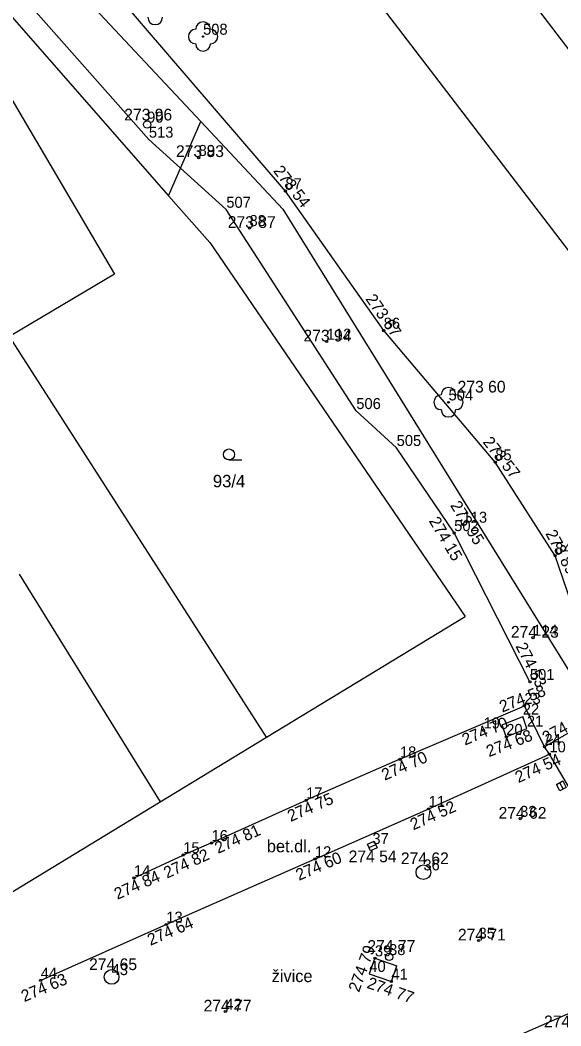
# Model space of a CAD drawing. Extents: x -492379 to -491966, y -1126153 to -1125860.
# Drawn here: x -492207.01 to -492184.88, y -1126038.78 to -1125997.58 of the extents above; entities that cross this region are included whole.
import ezdxf

# ---------------------------------------------------------------- set-up
doc = ezdxf.new("R2010")
doc.units = 0
for name, color, linetype in [('body', 7, 'Continuous'), ('hrana svahu', 7, 'Continuous'), ('kanalizace', 7, 'Continuous'), ('katastrální mapa', 7, 'Continuous'), ('ostatní objekty', 7, 'Continuous'), ('plot', 7, 'Continuous'), ('plyn', 7, 'Continuous'), ('podrobný výškový bod', 7, 'Continuous'), ('popis ploch', 7, 'Continuous'), ('rozhraní ploch', 7, 'Continuous'), ('silové vedení', 7, 'Continuous'), ('vodovod', 7, 'Continuous'), ('vstup na pozemek', 7, 'Continuous'), ('výšky', 7, 'Continuous'), ('čísla bodů', 7, 'Continuous')]:
    doc.layers.add(name, color=color, linetype=linetype)

msp = doc.modelspace()

# ---------------------------------------------------------------- linework, layer by layer
at = {"layer": 'body'}
for p, q in [((-492199.521, -1125998.258), (-492199.521, -1125998.258)), ((-492201.81, -1126001.858), (-492201.81, -1126001.858)), ((-492201.739, -1126002.474), (-492201.739, -1126002.474)), ((-492199.703, -1126003.222), (-492199.703, -1126003.222)), ((-492196.15, -1126004.585), (-492196.15, -1126004.585)), ((-492198.57, -1126005.345), (-492198.57, -1126005.345)), ((-492197.621, -1126006.096), (-492197.621, -1126006.096)), ((-492192.127, -1126010.3), (-492192.127, -1126010.3)), ((-492194.458, -1126010.749), (-492194.458, -1126010.749)), ((-492189.476, -1126013.237), (-492189.476, -1126013.237)), ((-492193.25, -1126013.59), (-492193.25, -1126013.59)), ((-492191.598, -1126015.101), (-492191.598, -1126015.101)), ((-492187.562, -1126015.688), (-492187.562, -1126015.688)), ((-492188.9, -1126018.244), (-492188.9, -1126018.244)), ((-492189.244, -1126018.589), (-492189.244, -1126018.589)), ((-492185.109, -1126019.52), (-492185.109, -1126019.52)), ((-492186.014, -1126022.877), (-492186.014, -1126022.877)), ((-492186.144, -1126024.687), (-492186.144, -1126024.687)), ((-492186.372, -1126025.666), (-492186.372, -1126025.666)), ((-492186.436, -1126026.104), (-492186.436, -1126026.104)), ((-492188.042, -1126026.672), (-492188.042, -1126026.672)), ((-492186.267, -1126026.598), (-492186.267, -1126026.598)), ((-492187.113, -1126026.937), (-492187.113, -1126026.937)), ((-492185.549, -1126027.345), (-492185.549, -1126027.345)), ((-492191.463, -1126027.86), (-492191.463, -1126027.86)), ((-492185.346, -1126027.649), (-492185.346, -1126027.649)), ((-492195.302, -1126029.538), (-492195.302, -1126029.538)), ((-492190.287, -1126029.887), (-492190.287, -1126029.887)), ((-492186.545, -1126030.293), (-492186.545, -1126030.293)), ((-492199.175, -1126031.285), (-492199.175, -1126031.285)), ((-492192.591, -1126031.407), (-492192.591, -1126031.407)), ((-492200.334, -1126031.781), (-492200.334, -1126031.781)), ((-492194.943, -1126031.947), (-492194.943, -1126031.947)), ((-492202.345, -1126032.721), (-492202.345, -1126032.721)), ((-492190.503, -1126032.485), (-492190.503, -1126032.485)), ((-492201.024, -1126034.624), (-492201.024, -1126034.624)), ((-492188.245, -1126035.281), (-492188.245, -1126035.281)), ((-492192.488, -1126036.005), (-492192.488, -1126036.005)), ((-492191.908, -1126035.954), (-492191.908, -1126035.954)), ((-492206.166, -1126036.917), (-492206.166, -1126036.917)), ((-492203.265, -1126036.774), (-492203.265, -1126036.774)), ((-492192.717, -1126036.642), (-492192.717, -1126036.642)), ((-492191.812, -1126036.96), (-492191.812, -1126036.96)), ((-492198.61, -1126038.189), (-492198.61, -1126038.189))]:
    msp.add_line(p, q, dxfattribs=at)
at = {"layer": 'hrana svahu'}
for p, q in [((-492196.15, -1126004.585), (-492205.259, -1125993.96)), ((-492192.127, -1126010.3), (-492196.15, -1126004.585)), ((-492187.562, -1126015.688), (-492192.127, -1126010.3)), ((-492185.109, -1126019.52), (-492187.562, -1126015.688)), ((-492183.695, -1126023.691), (-492185.109, -1126019.52))]:
    msp.add_line(p, q, dxfattribs=at)
at = {"layer": 'kanalizace'}
for p, q in [((-492184.929, -1126028.814), (-492184.787, -1126029.078)), ((-492192.728, -1126031.468), (-492192.454, -1126031.346))]:
    msp.add_line(p, q, dxfattribs=at)
for points in [[(-492184.797, -1126028.743), (-492184.655, -1126029.008), (-492184.92, -1126029.149), (-492185.062, -1126028.885)], [(-492192.789, -1126031.331), (-492192.515, -1126031.209), (-492192.393, -1126031.483), (-492192.667, -1126031.605)]]:
    msp.add_lwpolyline(points, close=True, dxfattribs=at)
for centre in [(-492190.503, -1126032.485), (-492203.265, -1126036.774)]:
    msp.add_circle(centre, 0.3, dxfattribs=at)
at = {"layer": 'katastrální mapa'}
for p, q in [((-492216.8, -1125983.38), (-492199.61, -1126001.74)), ((-492194.65, -1125985.54), (-492177.26, -1126008.38)), ((-492198.1, -1125989.34), (-492176.36, -1126017.77)), ((-492207.54, -1125997.23), (-492200.93, -1126004.78)), ((-492208.65, -1125998.64), (-492203.15, -1126007.99)), ((-492200.93, -1126004.78), (-492199.61, -1126001.74)), ((-492199.61, -1126001.74), (-492196.25, -1126005.33)), ((-492200.93, -1126004.78), (-492199.25, -1126006.69)), ((-492196.25, -1126005.33), (-492184.32, -1126024.61)), ((-492199.25, -1126006.69), (-492188.79, -1126022.01)), ((-492203.15, -1126007.99), (-492207.44, -1126010.54)), ((-492196.92, -1126026.95), (-492207.44, -1126010.54)), ((-492198.46, -1126015.6), (-492197.93, -1126015.6)), ((-492207.05, -1126020.28), (-492201.28, -1126029.6)), ((-492196.92, -1126026.95), (-492188.79, -1126022.01)), ((-492201.28, -1126029.6), (-492196.92, -1126026.95)), ((-492212.92, -1126036.68), (-492201.28, -1126029.6)), ((-492191.74, -1126041.4), (-492182.01, -1126037.16))]:
    msp.add_line(p, q, dxfattribs=at)
msp.add_circle((-492198.46, -1126015.375), 0.225, dxfattribs=at)
at = {"layer": 'ostatní objekty'}
for centre in [(-492199.521, -1125998.258), (-492189.476, -1126013.237)]:
    msp.add_circle(centre, 0.03, dxfattribs=at)
for centre, start, end in [((-492201.482, -1125997.469), 180, 0), ((-492199.521, -1125997.958), 0, 180), ((-492199.821, -1125998.258), 90, 270), ((-492199.221, -1125998.258), 270, 90), ((-492199.521, -1125998.558), 180, 0), ((-492189.476, -1126012.937), 0, 180), ((-492189.776, -1126013.237), 90, 270), ((-492189.176, -1126013.237), 270, 90), ((-492189.476, -1126013.537), 180, 0)]:
    msp.add_arc(centre, 0.3, start, end, dxfattribs=at)
at = {"layer": 'plot'}
for p, q in [((-492201.739, -1126002.474), (-492206.915, -1125996.619)), ((-492198.57, -1126005.345), (-492201.739, -1126002.474)), ((-492193.25, -1126013.59), (-492198.57, -1126005.345)), ((-492191.598, -1126015.101), (-492193.25, -1126013.59)), ((-492189.244, -1126018.589), (-492191.598, -1126015.101)), ((-492186.144, -1126024.687), (-492189.244, -1126018.589)), ((-492191.463, -1126027.86), (-492186.372, -1126025.666)), ((-492199.175, -1126031.285), (-492195.302, -1126029.538)), ((-492202.345, -1126032.721), (-492200.334, -1126031.781))]:
    msp.add_line(p, q, dxfattribs=at)
at = {"layer": 'plyn'}
msp.add_circle((-492201.81, -1126001.858), 0.15, dxfattribs=at)
at = {"layer": 'podrobný výškový bod'}
for centre in [(-492199.703, -1126003.222), (-492196.15, -1126004.585), (-492197.621, -1126006.096), (-492192.127, -1126010.3), (-492194.458, -1126010.749), (-492187.562, -1126015.688), (-492188.9, -1126018.244), (-492189.244, -1126018.589), (-492185.109, -1126019.52), (-492186.014, -1126022.877), (-492186.144, -1126024.687), (-492186.372, -1126025.666), (-492188.042, -1126026.672), (-492187.113, -1126026.937), (-492185.549, -1126027.345), (-492191.463, -1126027.86), (-492185.346, -1126027.649), (-492195.302, -1126029.538), (-492190.287, -1126029.887), (-492186.545, -1126030.293), (-492199.175, -1126031.285), (-492200.334, -1126031.781), (-492194.943, -1126031.947), (-492202.345, -1126032.721), (-492201.024, -1126034.624), (-492188.245, -1126035.281), (-492192.488, -1126036.005), (-492206.166, -1126036.917), (-492191.812, -1126036.96), (-492198.61, -1126038.189)]:
    msp.add_circle(centre, 0.045, dxfattribs=at)
at = {"layer": 'rozhraní ploch'}
for p, q in [((-492182.164, -1126025.391), (-492185.549, -1126027.345)), ((-492185.549, -1126027.345), (-492186.372, -1126025.666)), ((-492185.346, -1126027.649), (-492185.549, -1126027.345)), ((-492190.287, -1126029.887), (-492185.346, -1126027.649)), ((-492183.251, -1126031.227), (-492185.346, -1126027.649)), ((-492194.943, -1126031.947), (-492190.287, -1126029.887)), ((-492194.943, -1126031.947), (-492201.024, -1126034.624)), ((-492201.024, -1126034.624), (-492206.166, -1126036.917))]:
    msp.add_line(p, q, dxfattribs=at)
at = {"layer": 'silové vedení'}
for p, q in [((-492187.282, -1126026.443), (-492186.436, -1126026.104)), ((-492186.267, -1126026.598), (-492186.436, -1126026.104)), ((-492187.113, -1126026.937), (-492187.282, -1126026.443)), ((-492187.113, -1126026.937), (-492186.267, -1126026.598))]:
    msp.add_line(p, q, dxfattribs=at)
at = {"layer": 'vodovod'}
for p, q in [((-492192.488, -1126036.005), (-492192.717, -1126036.642)), ((-492192.488, -1126036.005), (-492191.588, -1126036.321)), ((-492191.812, -1126036.96), (-492191.588, -1126036.321)), ((-492192.717, -1126036.642), (-492191.812, -1126036.96))]:
    msp.add_line(p, q, dxfattribs=at)
msp.add_circle((-492191.908, -1126035.954), 0.15, dxfattribs=at)
at = {"layer": 'vstup na pozemek'}
for p, q in [((-492191.463, -1126027.86), (-492195.302, -1126029.538)), ((-492199.175, -1126031.285), (-492200.334, -1126031.781))]:
    msp.add_line(p, q, dxfattribs=at)

# ---------------------------------------------------------------- texts
at = {"layer": 'katastrální mapa'}
msp.add_text('93/4', height=0.51, dxfattribs=at).set_placement((-492199.12, -1126016.72))
at = {"layer": 'popis ploch'}
for s, p in [('bet.dl.', (-492196.91, -1126031.667)), ('živice', (-492196.713, -1126036.984))]:
    msp.add_text(s, height=0.5, dxfattribs=at).set_placement(p)
at = {"layer": 'výšky'}
for s, p in [('273 96', (-492202.749, -1126001.694)), ('273 83', (-492200.63, -1126003.193)), ('273 87', (-492198.511, -1126006.096)), ('273 94', (-492195.413, -1126010.746)), ('273 60', (-492189.104, -1126012.838)), ('274 23', (-492186.923, -1126022.878)), ('274 62', (-492187.427, -1126030.293)), ('274 54', (-492193.564, -1126032.075)), ('274 62', (-492191.426, -1126032.154)), ('274 71', (-492189.091, -1126035.281)), ('274 77', (-492192.798, -1126035.747)), ('274 65', (-492204.186, -1126036.493)), ('274 77', (-492199.5, -1126038.189)), ('274 73', (-492185.567, -1126038.835))]:
    msp.add_text(s, height=0.48, dxfattribs=at).set_placement(p)
for s, rotation, p in [('273 54', 307.94, (-492196.671, -1126003.765)), ('273 67', 305.0253, (-492192.89, -1126009.009)), ('273 57', 308.2492, (-492188.095, -1126014.872)), ('273 95', 301.7497, (-492189.422, -1126017.458)), ('274 15', 300.5855, (-492190.292, -1126018.096)), ('273 89', 298.1924, (-492185.522, -1126018.61)), ('274 53', 296.9149, (-492186.743, -1126023.225)), ('274 58', 21.5177, (-492187.278, -1126025.95)), ('274 70', 22.7225, (-492188.802, -1126027.3)), ('274 54', 28.5451, (-492185.477, -1126027.214)), ('274 68', 21.1447, (-492187.82, -1126027.774)), ('274 70', 23.8541, (-492192.086, -1126028.74)), ('274 54', 24.0904, (-492186.617, -1126028.838)), ('274 75', 23.327, (-492195.94, -1126030.428)), ('274 52', 24.1679, (-492190.914, -1126030.772)), ('274 81', 24.1428, (-492198.91, -1126031.737)), ('274 82', 24.6097, (-492201.001, -1126032.752)), ('274 60', 23.2131, (-492195.6, -1126032.839)), ('274 84', 23.7682, (-492203.03, -1126033.619)), ('274 64', 23.0399, (-492201.676, -1126035.5)), ('274 79', 69.9339, (-492193.14, -1126037.43)), ('274 63', 23.0481, (-492206.841, -1126037.809)), ('274 77', 340.6357, (-492192.849, -1126037.214))]:
    msp.add_text(s, height=0.48, rotation=rotation, dxfattribs=at).set_placement(p)
at = {"layer": 'čísla bodů'}
for s, p in [('508', (-492199.521, -1125998.183)), ('90', (-492201.81, -1126001.783)), ('513', (-492201.739, -1126002.399)), ('89', (-492199.703, -1126003.147)), ('87', (-492196.15, -1126004.51)), ('507', (-492198.57, -1126005.27)), ('88', (-492197.621, -1126006.021)), ('86', (-492192.127, -1126010.225)), ('112', (-492194.458, -1126010.674)), ('506', (-492193.25, -1126013.515)), ('504', (-492189.476, -1126013.162)), ('505', (-492191.598, -1126015.026)), ('85', (-492187.562, -1126015.613)), ('113', (-492188.9, -1126018.169)), ('502', (-492189.244, -1126018.514)), ('84', (-492185.109, -1126019.445)), ('114', (-492186.014, -1126022.802)), ('501', (-492186.144, -1126024.612)), ('23', (-492186.372, -1126025.591)), ('22', (-492186.436, -1126026.029)), ('19', (-492188.042, -1126026.597)), ('21', (-492186.267, -1126026.523)), ('20', (-492187.113, -1126026.862)), ('24', (-492185.549, -1126027.27)), ('18', (-492191.463, -1126027.785)), ('10', (-492185.346, -1126027.574)), ('17', (-492195.302, -1126029.463)), ('11', (-492190.287, -1126029.812)), ('33', (-492186.545, -1126030.218)), ('16', (-492199.175, -1126031.21)), ('37', (-492192.591, -1126031.332)), ('15', (-492200.334, -1126031.706)), ('12', (-492194.943, -1126031.872)), ('36', (-492190.503, -1126032.41)), ('14', (-492202.345, -1126032.646)), ('13', (-492201.024, -1126034.549)), ('35', (-492188.245, -1126035.206)), ('39', (-492192.488, -1126035.93)), ('38', (-492191.908, -1126035.879)), ('40', (-492192.717, -1126036.567)), ('44', (-492206.166, -1126036.842)), ('43', (-492203.265, -1126036.699)), ('41', (-492191.812, -1126036.885)), ('42', (-492198.61, -1126038.114))]:
    msp.add_text(s, height=0.45, dxfattribs=at).set_placement(p)

doc.saveas('drawing.dxf')
